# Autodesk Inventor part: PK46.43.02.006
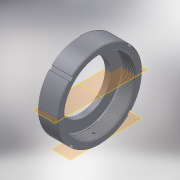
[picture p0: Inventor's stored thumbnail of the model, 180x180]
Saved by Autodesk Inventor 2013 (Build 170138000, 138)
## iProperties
Shininess: 64.0
Length Units: 11269
Angle Units: 11279
Time Units: 11290
Mass Units: 11283
Length Display Precision: 3
Angle Display Precision: 2
Compacted: True
Part Number: PK46.43.02.006
Document SubType Name: Modeling
Created: 2004-11
Material: Сталь высокопрочная низколегированная
Designer: ELarisa
Manufacturer: Standard
Standards Organization: Custom
Density: 7.84 g/cm^3
Mass: 6438.98 g
Surface Area: 1201.69 cm^2
Volume: 821.298 cm^3
Density: 0.0
Volumn: 0.0
Area: 0.0
PropertySet Name: Model Information
Control State: 0
Master: False
Checked Out: False
Checked Out Date: 2008-10-09
Last Check In Date: 2008-10-09
Author: ELarisa
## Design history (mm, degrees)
sketch "Эскиз1"
  geometry: L1 (-39.127, -64.027)-(-39.127, 48.473); L2 (-39.127, 48.473)-(15.873, 48.473); L3 (15.873, 48.473)-(15.873, -64.027); L4 (15.873, -64.027)-(-39.127, -64.027); L5 (-39.127, 3.473)-(-24.127, 3.473); L6 (-24.127, 3.473)-(-24.127, 31.473); L7 (-24.127, 31.473)-(-20.127, 31.473); L8 (-20.127, 31.473)-(-19.627, 30.973); L9 (-19.627, 30.973)-(15.873, 30.973)
  constraints: 18 end point, 4 parallel, 3 perpendicular, 2 point on line, 1 vertical
  dimensions: "d0" = 55 distance of L3.end L1.start; "d1" = 112.5 distance of L1.start L1.end; "d2" = 95.5 distance from line of L6.end L4; "d3" = 67.5 distance between parallel lines of L4 L5; "d4" = 95 distance between parallel lines of L4 L9; "d5" = 40 distance between parallel lines of L3 L6; "d6" = 4 distance of L6.end L7.end; "d7" = 135 deg angle of L9 L8
revolve "Вращение1" sketch "Эскиз1" stored, may be unused: angle "d8" = 90 deg
chamfer "Фаска1" distance "d9" = 2; stored, may be unused: second distance "d10" = 2, angle "d50" = 45 deg
feature "Резьба2" dims "d13" = 10, "d14" = 0
chamfer "Фаска2" distance "d15" = 2; stored, may be unused: second distance "d16" = 2, angle "d51" = 45 deg
node "РабОсь1"
node "РабПлоскость1"
sketch "Эскиз2"
  geometry: L1 (-71.163, -64.027)-(153.091, -64.027) reference; L2 (-37.127, 48.473)-(-37.127, -176.527) reference; 2 further points
  dimensions: "d18" = 0 distance from line of L1 point (-2.127, -64.027); "d19" = 35 distance from line of L2 point (-2.127, -64.027)
hole "Отверстие1" sketch "Эскиз2" at (-2.127, -64.027), (121.054, 48.551) diameter "d20" = 6.647; stored, may be unused: countersink angle "d24" = 82 deg, drill point angle "d26" = 118 deg; dims "d21" = 15, "d22" = 11.2, "d23" = 2, "d25" = 20
sketch "Эскиз4"
  geometry: L1 (0, 0)-(-112.708, 0); L2 (0, 0)-(-104.857, -104.857); L3 (-72.478, -79.55)-(-76.014, -76.014); L4 (-76.014, -76.014)-(-79.55, -72.478); L5 (-79.55, -72.478)-(-86.621, -79.55); L6 (-86.621, -79.55)-(-79.55, -86.621); L7 (-79.55, -86.621)-(-72.478, -79.55); C1 r 67.5 at (0, 0) reference; C2 r 110.5 at (0, 0) reference
  constraints: 14 end point, 2 parallel, 2 perpendicular, 1 collinear, 1 horizontal, 1 point on line
  dimensions: "d40" = 45 deg angle of L2 L1; "d41" = 5 distance of L3.start L3.end; "d42" = 5 distance of L3.end L4.end; "d43" = 10 distance of L6.end L3.start; "d44" = 107.5 distance from line of C1.centre L4
extrude "Выдавливание2" cut sketch "Эскиз4" stored distance "d45" = 10; taper "d46" = 0 deg
pattern_circular "Круговой массив2" dims angle "d49" = 360 deg
body "Solid1"
other parameters: "d17" = -112.5
